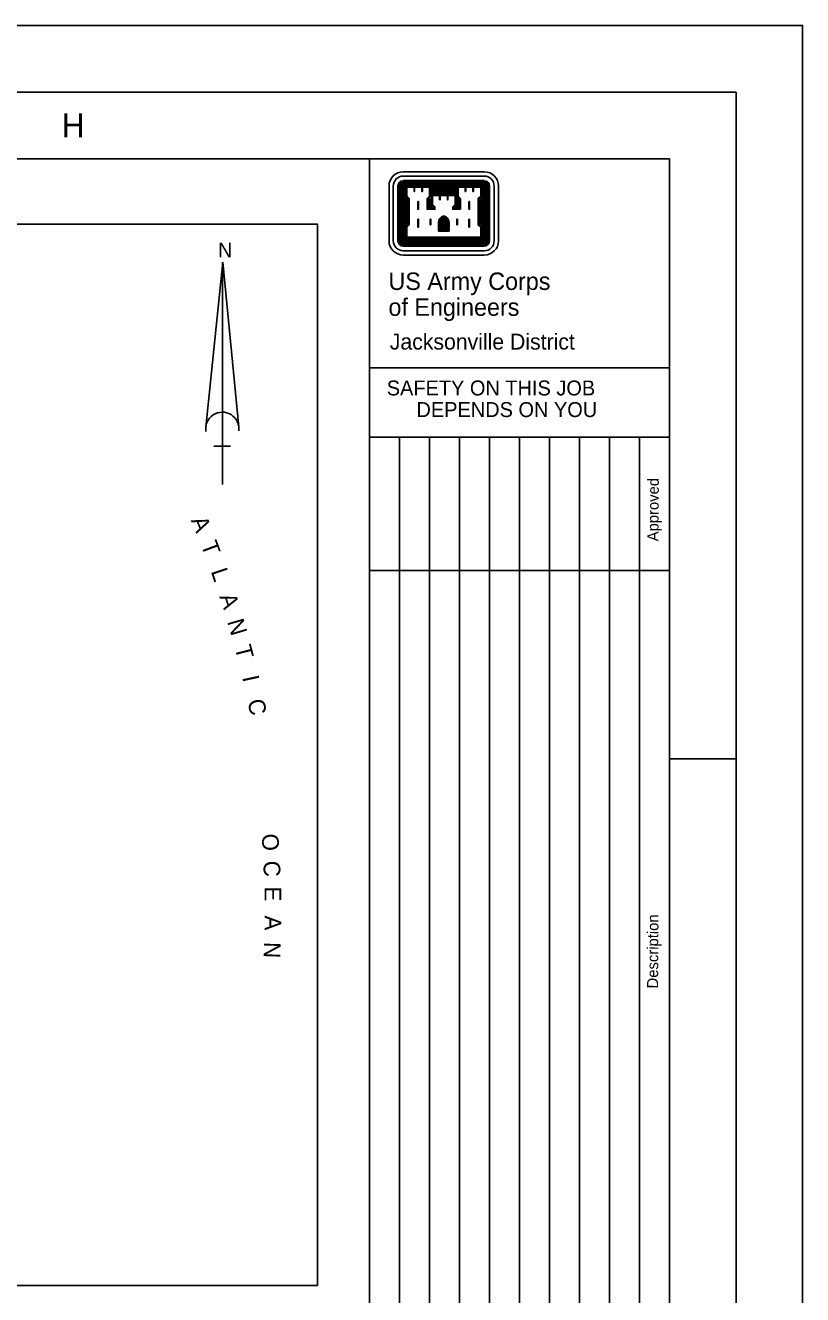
# Model space of a CAD drawing. Extents: x 492225 to 553725, y 1303773 to 1347273.
# Drawn here: x 544976 to 553725, y 1332996 to 1347273 of the extents above; entities that cross this region are included whole.
import ezdxf

# ---------------------------------------------------------------- set-up
doc = ezdxf.new("R2010")
doc.units = 0
for name, color, linetype in [('G-ANNO-SYMB', 7, 'Continuous'), ('G-ANNO-TEXT', 7, 'Continuous'), ('G-ANNO-TTLB', 7, 'Continuous'), ('Level 2', 7, 'Continuous'), ('Level 20', 7, 'Continuous'), ('Level 63', 7, 'Continuous')]:
    doc.layers.add(name, color=color, linetype=linetype)

msp = doc.modelspace()

# ---------------------------------------------------------------- linework, layer by layer
at = {"layer": 'G-ANNO-SYMB'}
for p, q in [((550141.569, 1345625.564), (549229.569, 1345625.564)), ((549069.069, 1345465.064), (549069.069, 1344850.064)), ((549117.069, 1344850.064), (549117.069, 1345465.064)), ((549169.569, 1345465.064), (549169.569, 1344850.064)), ((549183.069, 1345465.064), (549183.069, 1344850.064)), ((549195.069, 1345465.064), (549195.069, 1344850.064)), ((549208.569, 1345465.064), (549208.569, 1344850.064)), ((549222.069, 1345465.064), (549222.069, 1344850.064)), ((549229.569, 1345577.564), (550141.569, 1345577.564)), ((550141.569, 1345526.564), (549229.569, 1345526.564)), ((550141.569, 1345513.064), (549229.569, 1345513.064)), ((550141.569, 1345499.564), (549229.569, 1345499.564)), ((550141.569, 1345487.564), (549229.569, 1345487.564)), ((550141.569, 1345474.064), (549229.569, 1345474.064)), ((549235.569, 1345465.064), (549235.569, 1344854.564)), ((549247.569, 1345465.064), (549247.569, 1344868.064)), ((549546.069, 1345462.064), (549825.069, 1345462.064)), ((549546.069, 1345448.564), (549825.069, 1345448.564)), ((550123.569, 1345465.064), (550123.569, 1344868.064)), ((550135.569, 1345465.064), (550135.569, 1344854.564)), ((550149.069, 1345465.064), (550149.069, 1344850.064)), ((550162.569, 1345465.064), (550162.569, 1344850.064)), ((550174.569, 1345465.064), (550174.569, 1344850.064)), ((550188.069, 1345465.064), (550188.069, 1344850.064)), ((550201.569, 1345465.064), (550201.569, 1344850.064)), ((550252.569, 1345465.064), (550252.569, 1344850.064)), ((550302.069, 1344850.064), (550302.069, 1345465.064)), ((549258.069, 1345334.564), (549258.069, 1345019.564)), ((549271.569, 1345321.064), (549271.569, 1345034.564)), ((549546.069, 1345436.564), (549825.069, 1345436.564)), ((549546.069, 1345423.064), (549825.069, 1345423.064)), ((549546.069, 1345409.564), (549825.069, 1345409.564)), ((549546.069, 1345397.564), (549825.069, 1345397.564)), ((549546.069, 1345384.064), (549825.069, 1345384.064)), ((550099.569, 1345321.064), (550099.569, 1345034.564)), ((550113.069, 1345333.064), (550113.069, 1345021.064)), ((549625.569, 1344956.564), (549625.569, 1345057.064)), ((549637.569, 1344956.564), (549637.569, 1345057.064)), ((549651.069, 1344956.564), (549651.069, 1345057.064)), ((549664.569, 1344956.564), (549664.569, 1345057.064)), ((549676.569, 1344956.564), (549676.569, 1345057.064)), ((549694.569, 1344956.564), (549694.569, 1345057.064)), ((549706.569, 1344956.564), (549706.569, 1345057.064)), ((549720.069, 1344956.564), (549720.069, 1345057.064)), ((549733.569, 1344956.564), (549733.569, 1345057.064)), ((549745.569, 1344956.564), (549745.569, 1345057.064)), ((549625.569, 1344956.564), (549745.569, 1344956.564)), ((550141.569, 1344841.064), (549229.569, 1344841.064)), ((550141.569, 1344829.064), (549229.569, 1344829.064)), ((550141.569, 1344815.564), (549229.569, 1344815.564)), ((550141.569, 1344802.064), (549229.569, 1344802.064)), ((550141.569, 1344790.064), (549229.569, 1344790.064)), ((550141.569, 1344737.564), (549229.569, 1344737.564)), ((550135.569, 1344854.564), (549235.569, 1344854.564)), ((550123.569, 1344868.064), (549247.569, 1344868.064)), ((549229.569, 1344688.064), (550141.569, 1344688.064))]:
    msp.add_line(p, q, dxfattribs=at)
for points in [[(549258.069, 1345465.064), (549258.069, 1345346.564), (549283.569, 1345321.064), (549283.569, 1345034.564), (549258.069, 1345007.564), (549258.069, 1344877.064), (550113.069, 1344877.064), (550113.069, 1345007.564), (550086.069, 1345034.564), (550086.069, 1345321.064), (550113.069, 1345346.564), (550113.069, 1345465.064), (550000.569, 1345465.064), (549913.569, 1345465.064), (549832.569, 1345465.064), (549832.569, 1345346.564), (549861.069, 1345321.064), (549861.069, 1345216.064), (549798.069, 1345216.064), (549798.069, 1345226.564), (549825.069, 1345253.564), (549825.069, 1345370.564), (549712.569, 1345370.564), (549625.569, 1345370.564), (549546.069, 1345370.564), (549546.069, 1345253.564), (549573.069, 1345226.564), (549573.069, 1345216.064), (549510.069, 1345216.064), (549510.069, 1345321.064), (549537.069, 1345346.564), (549537.069, 1345465.064), (549424.569, 1345465.064), (549337.569, 1345465.064), (549258.069, 1345465.064)], [(549270.069, 1345451.564), (549270.069, 1345352.564), (549297.069, 1345325.564), (549297.069, 1345028.564), (549270.069, 1345001.564), (549270.069, 1344890.564), (550101.069, 1344890.564), (550101.069, 1345001.564), (550072.569, 1345028.564), (550072.569, 1345325.564), (550101.069, 1345352.564), (550101.069, 1345451.564), (550020.069, 1345451.564), (550020.069, 1345405.064), (550012.569, 1345405.064), (550012.569, 1345451.564), (549933.069, 1345451.564), (549933.069, 1345405.064), (549927.069, 1345405.064), (549927.069, 1345451.564), (549846.069, 1345451.564), (549846.069, 1345352.564), (549873.069, 1345325.564), (549873.069, 1345204.064), (549786.069, 1345204.064), (549786.069, 1345232.564), (549813.069, 1345259.564), (549813.069, 1345358.564), (549732.069, 1345358.564), (549732.069, 1345312.064), (549726.069, 1345312.064), (549726.069, 1345358.564), (549645.069, 1345358.564), (549645.069, 1345312.064), (549637.569, 1345312.064), (549637.569, 1345358.564), (549558.069, 1345358.564), (549558.069, 1345259.564), (549585.069, 1345232.564), (549585.069, 1345204.064), (549498.069, 1345204.064), (549498.069, 1345325.564), (549525.069, 1345352.564), (549525.069, 1345451.564), (549445.569, 1345451.564), (549445.569, 1345405.064), (549438.069, 1345405.064), (549438.069, 1345451.564), (549357.069, 1345451.564), (549357.069, 1345405.064), (549351.069, 1345405.064), (549351.069, 1345451.564), (549270.069, 1345451.564)], [(549531.069, 1345322.564), (549523.569, 1345315.064), (549523.569, 1345229.564), (549552.069, 1345229.564), (549532.569, 1345249.064), (549532.569, 1345324.064)], [(549840.069, 1345322.564), (549847.569, 1345315.064), (549847.569, 1345229.564), (549820.569, 1345229.564), (549838.569, 1345249.064), (549838.569, 1345324.064)], [(549393.069, 1345291.064), (549393.069, 1345204.064), (549402.069, 1345204.064), (549402.069, 1345291.064), (549393.069, 1345291.064)], [(549976.569, 1345291.064), (549976.569, 1345204.064), (549969.069, 1345204.064), (549969.069, 1345291.064), (549976.569, 1345291.064)], [(549393.069, 1345091.564), (549393.069, 1345003.064), (549402.069, 1345003.064), (549402.069, 1345091.564), (549393.069, 1345091.564)], [(549531.069, 1345091.564), (549531.069, 1345030.064), (549538.569, 1345030.064), (549538.569, 1345091.564), (549531.069, 1345091.564)], [(549840.069, 1345091.564), (549840.069, 1345030.064), (549832.569, 1345030.064), (549832.569, 1345091.564), (549840.069, 1345091.564)], [(549976.569, 1345091.564), (549976.569, 1345003.064), (549969.069, 1345003.064), (549969.069, 1345091.564), (549976.569, 1345091.564)]]:
    msp.add_lwpolyline(points, dxfattribs=at)
for centre, major_axis, ratio, start_param, end_param in [((549229.9501, 1345465.3215), (160.7078, 0), 0.9996399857, 1.5707800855, 3.1415763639), ((550140.6277, 1345465.3072), (160.7078, 0), 0.9996399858, 6.2831691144, 7.8539653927), ((549229.9501, 1345465.3215), (112.3481, 0), 0.9996399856, 1.5707800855, 3.1415763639), ((549229.9501, 1345465.3215), (60.2655, 0), 0.9996399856, 1.5707800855, 3.1415763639), ((549229.9501, 1345465.3215), (47.2451, 0), 0.9996399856, 1.5707800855, 3.1415763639), ((549229.9501, 1345465.3215), (34.2248, 0), 0.9996399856, 1.5707800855, 3.1415763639), ((549229.9501, 1345465.3215), (21.2045, 0), 0.9996399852, 1.5707800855, 3.1415763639), ((549229.9501, 1345465.3215), (8.1841, 0), 0.9996399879, 1.5707800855, 3.1415763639), ((550140.6277, 1345465.3072), (8.1841, 0), 0.9996399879, 6.2831691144, 7.8539653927), ((550140.6277, 1345465.3072), (21.2045, 0), 0.9996399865, 6.2831691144, 7.8539653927), ((550140.6277, 1345465.3072), (34.2248, 0), 0.9996399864, 6.2831691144, 7.8539653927), ((550140.6277, 1345465.3072), (47.2451, 0), 0.9996399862, 6.2831691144, 7.8539653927), ((550140.6277, 1345465.3072), (60.2655, 0), 0.9996399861, 6.2831691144, 7.8539653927), ((550140.6277, 1345465.3072), (112.3481, 0), 0.9996399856, 6.2831695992, 7.8539658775), ((549707.7195, 1345050.3752), (-83.3017, 0), 0.9996399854, 4.9858321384, 6.2143593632), ((549707.7195, 1345050.3752), (-70.2813, 0), 0.9996399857, 4.9474654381, 6.2143596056), ((549707.7195, 1345050.3752), (-57.261, 0), 0.9996399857, 4.9474654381, 6.2143596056), ((549707.7195, 1345050.3752), (-44.2407, 0), 0.9996399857, 4.9474653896, 6.2143595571), ((549662.8453, 1345050.3759), (31.2204, 0), 0.9996399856, 0.0687944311, 1.3356885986), ((549662.8453, 1345050.3759), (44.2407, 0), 0.9996399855, 0.0687944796, 1.3356886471), ((549662.8453, 1345050.3759), (57.261, 0), 0.9996399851, 0.0687948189, 1.3356889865), ((549707.7195, 1345050.3752), (-31.2204, 0), 0.9996399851, 4.9474649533, 6.2143591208), ((549662.8453, 1345050.3759), (70.2813, 0), 0.9996399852, 0.068794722, 1.3356888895), ((549662.8453, 1345050.3759), (83.3017, 0), 0.9996399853, 0.0687946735, 1.2984199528), ((549229.9404, 1344849.497), (-160.7078, 0), 0.9996399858, 6.283170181, 7.8539664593), ((549229.9404, 1344849.497), (-112.3481, 0), 0.9996399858, 6.2831695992, 7.8539658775), ((549229.9404, 1344849.497), (-60.2655, 0), 0.9996399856, 6.283170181, 7.8539664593), ((549229.9404, 1344849.497), (-47.2451, 0), 0.9996399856, 6.283170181, 7.8539664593), ((549229.9404, 1344849.497), (-34.2248, 0), 0.9996399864, 6.283170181, 7.8539664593), ((549229.9404, 1344849.497), (-21.2045, 0), 0.9996399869, 6.283170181, 7.8539664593), ((549229.9404, 1344849.497), (-8.1841, 0), 0.999639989, 6.283170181, 7.8539664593), ((550140.618, 1344849.4827), (160.7078, 0), 0.9996399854, 4.7123733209, 6.2831695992), ((550140.618, 1344849.4827), (-112.3481, 0), 0.9996399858, 1.5707811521, 3.1415774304), ((550140.618, 1344849.4827), (60.2655, 0), 0.9996399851, 4.7123733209, 6.2831695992), ((550140.618, 1344849.4827), (47.2451, 0), 0.999639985, 4.7123733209, 6.2831695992), ((550140.618, 1344849.4827), (34.2248, 0), 0.9996399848, 4.7123733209, 6.2831695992), ((550140.618, 1344849.4827), (21.2045, 0), 0.9996399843, 4.7123733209, 6.2831695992), ((550140.618, 1344849.4827), (8.1841, 0), 0.9996399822, 4.7123733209, 6.2831695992)]:
    msp.add_ellipse(centre, major_axis=major_axis, ratio=ratio, start_param=start_param, end_param=end_param, dxfattribs=at)
at = {"layer": 'G-ANNO-TTLB'}
for p, q in [((552975.069, 1346522.564), (492975.069, 1346522.564)), ((552975.069, 1304522.564), (552975.069, 1346522.564)), ((494850.069, 1345772.564), (552225.069, 1345772.564)), ((548850.069, 1305272.564), (548850.069, 1345772.564)), ((552225.069, 1345772.564), (552225.069, 1305272.564)), ((552225.069, 1343422.064), (548850.069, 1343422.064)), ((549187.569, 1330642.064), (549187.569, 1342640.564)), ((549525.069, 1330642.064), (549525.069, 1342640.564)), ((549862.569, 1330642.064), (549862.569, 1342640.564)), ((550200.069, 1330642.064), (550200.069, 1342640.564)), ((550537.569, 1330642.064), (550537.569, 1342640.564)), ((550875.069, 1330642.064), (550875.069, 1342640.564)), ((551212.569, 1330642.064), (551212.569, 1342640.564)), ((551550.069, 1330642.064), (551550.069, 1342640.564)), ((551887.569, 1330642.064), (551887.569, 1342640.564)), ((548850.069, 1341140.564), (552225.069, 1341140.564)), ((552975.069, 1339022.564), (552225.069, 1339022.564))]:
    msp.add_line(p, q, dxfattribs=at)
for points in [[(492225.069, 1303772.564), (553725.069, 1303772.564), (553725.069, 1347272.564), (492225.069, 1347272.564)], [(492225.069, 1303772.564), (553725.069, 1303772.564), (553725.069, 1347272.564), (492225.069, 1347272.564)], [(492225.069, 1347272.564), (553725.069, 1347272.564), (553725.069, 1303772.564), (492225.069, 1303772.564)]]:
    msp.add_lwpolyline(points, close=True, dxfattribs=at)
for points in [[(553350.069, 1347272.564), (553725.069, 1347272.564), (553725.069, 1346897.564)], [(552225.069, 1342640.564), (548850.069, 1342640.564)]]:
    msp.add_lwpolyline(points, dxfattribs=at)
at = {"layer": 'Level 2'}
for p, q in [((547006.4695, 1342753.6405), (547199.4695, 1344608.5155)), ((547379.5945, 1342752.3905), (547198.3445, 1344609.7655)), ((547098.5945, 1342540.2655), (547286.0945, 1342540.2655))]:
    msp.add_line(p, q, dxfattribs=at)
msp.add_lwpolyline([(547192.9695, 1342109.1405), (547192.9695, 1344609.1405)], dxfattribs=at)
msp.add_arc((547192.9408, 1342734.203), 187.5, 353.34585278, 188.79083056, dxfattribs=at)
at = {"layer": 'Level 63'}
msp.add_lwpolyline([(534984.2995, 1333099.493), (548263.6245, 1333099.498), (548263.6245, 1345038.098), (534984.2995, 1345038.093)], close=True, dxfattribs=at)

# ---------------------------------------------------------------- texts
at = {"layer": 'G-ANNO-TEXT'}
for s, height, p in [('US Army Corps', 196.29, (549063.069, 1344296.564)), ('of Engineers', 196.29, (549063.069, 1344005.564)), ('Jacksonville District', 178.497, (549078.069, 1343626.064)), ('SAFETY ON THIS JOB', 167.976, (549043.569, 1343110.064)), ('DEPENDS ON YOU', 167.976, (549378.069, 1342867.064))]:
    msp.add_text(s, height=height, dxfattribs=at).set_placement(p)
for s, height, p in [('Approved', 124.497, (552102.069, 1341469.064)), ('Description', 124.488, (552097.569, 1336439.564))]:
    msp.add_text(s, height=height, rotation=89.66090001, dxfattribs=at).set_placement(p)
at = {"layer": 'G-ANNO-TTLB'}
msp.add_text('H', height=267.507, dxfattribs=at).set_placement((545385.069, 1346014.064))
at = {"layer": 'Level 2'}
msp.add_text('N', height=164.0625, dxfattribs=at).set_placement((547145.4695, 1344664.2655))
at = {"layer": 'Level 20'}
for s, height, rotation, p in [('A', 187.4992, 292.60925783, (546836.9645, 1341705.5205)), ('T', 187.5, 290.55820305, (546948.2145, 1341433.0205)), ('L', 187.5, 288.50714828, (547061.9645, 1341133.0205)), ('A', 187.5, 288.50714828, (547158.2145, 1340849.2705)), ('N', 187.4992, 286.45609353, (547245.7145, 1340566.7705)), ('T', 187.5, 284.40503876, (547329.4645, 1340278.0205)), ('I', 187.5, 282.35398397, (547415.7145, 1339940.5205)), ('C', 187.5, 282.35398397, (547474.4645, 1339674.2705)), ('O', 187.5, 274.14976491, (547634.4045, 1338174.2705)), ('C', 187.5, 272.09871016, (547654.4045, 1337873.0205)), ('E', 187.4992, 270.0476554, (547668.1545, 1337586.7705)), ('A', 187.4992, 270.0476554, (547668.1545, 1337260.5205)), ('N', 187.4992, 268.09990898, (547663.1545, 1336964.2705))]:
    msp.add_text(s, height=height, rotation=rotation, dxfattribs=at).set_placement(p)

doc.saveas('drawing.dxf')
